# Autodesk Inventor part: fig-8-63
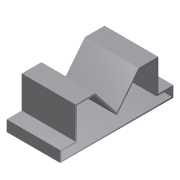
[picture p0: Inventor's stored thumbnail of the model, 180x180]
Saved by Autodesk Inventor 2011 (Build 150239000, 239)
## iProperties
Shininess: 77.0
Length Units: 11269
Angle Units: 11279
Time Units: 11290
Mass Units: 11283
Length Display Precision: 3
Angle Display Precision: 2
Created: 2002-01
Part Number: fig-8-63
Document SubType Name: Modeling
Designer: ***
Density: 1 g/cm^3
Density: 0.0
Volumn: 0.0
Area: 0.0
PropertySet Name: Model Information
Control State: 0
Master: False
Checked Out: False
Author: ***
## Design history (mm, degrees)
node "Sketch1"
sketch "Sketch2"
  geometry: L1 (0, 0)-(-14.184, 17.961); L2 (-14.184, 17.961)-(-26.987, 17.961); L3 (-26.987, 17.961)-(-26.987, -2.947); L4 (-26.987, -2.947)-(-36.842, -2.947); L5 (-36.842, -2.947)-(-36.842, -10.132); L6 (26.987, 17.961)-(26.987, -2.947); L7 (14.184, 17.961)-(26.987, 17.961); L8 (26.987, -2.947)-(36.842, -2.947); L9 (36.842, -10.132)-(-36.842, -10.132); L10 (36.842, -2.947)-(36.842, -10.132); L11 (0, 0)-(14.184, 17.961)
  constraints: 22 end point, 2 horizontal, 2 parallel, 1 perpendicular
extrude "Extrusion1" new body sketch "Sketch2" distance "d0" = 35; taper "d1" = 0 deg
shell "Shell3" dims "d13" = 1
body "Solid1"
